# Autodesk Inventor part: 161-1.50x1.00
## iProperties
Created: 2007-06
Part Number: 161-1.50x1.00
Document SubType Name: Modeling
Designer: btaylor
Density: 1 g/cm^3
Author: btaylor
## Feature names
1. Extrusion1
2. Extrusion2
3. Extrusion3
4. Extrusion4
5. Extrusion5
6. Fillet1
7. Fillet2
8. Extrusion6
9. Extrusion7
10. Extrusion8
11. Extrusion9
12. Extrusion10
13. Fillet3
14. Fillet4
15. Chamfer1
16. Chamfer2
17. Chamfer3
18. Fillet5
19. Fillet6
20. Fillet7
21. Fillet8
22. Fillet9
23. Fillet10
24. Fillet11
